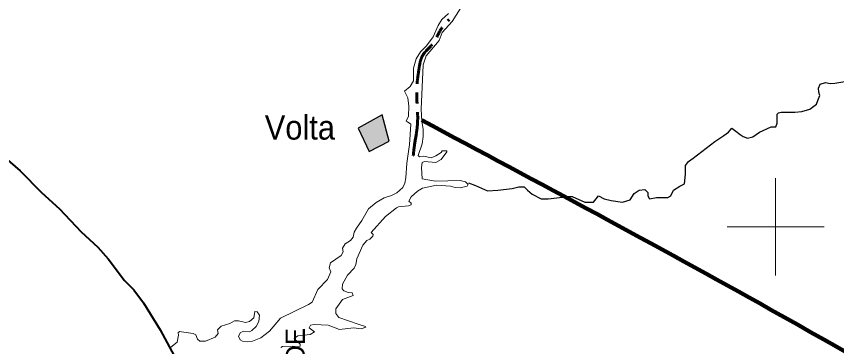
# Model space of a CAD drawing. Extents: x 553962 to 842807, y 8883888 to 9032388.
# Drawn here: x 584337 to 601258, y 8972533 to 8979336 of the extents above; entities that cross this region are included whole.
import ezdxf

# ---------------------------------------------------------------- set-up
doc = ezdxf.new("R2010")
doc.units = 0
doc.header["$LTSCALE"] = 150
doc.linetypes.add('LONG_DASH_SHORT_DASH', pattern=[9.9, 6, -1.2, 1.5, -1.2])
for name, color, linetype, lineweight in [('12', 7, 'Continuous', 25), ('2', 7, 'Continuous', 13), ('21', 7, 'Continuous', 25), ('24', 7, 'Continuous', 25), ('25', 7, 'Continuous', 13), ('7', 7, 'LONG_DASH_SHORT_DASH', 60), ('9', 7, 'Continuous', 90)]:
    doc.layers.add(name, color=color, linetype=linetype, lineweight=lineweight)
doc.layers.add('41', color=7, linetype='Continuous')
doc.layers.add('50', color=7, linetype='Continuous')

msp = doc.modelspace()

# ---------------------------------------------------------------- hatches: boundary and pattern name
at = {"layer": '21'}
msp.add_hatch(color=256, dxfattribs=at).paths.add_polyline_path([(591387.2, 8977029.8), (591614.3, 8976550.1), (592028.7, 8976768.6), (591880.1, 8977309.9)])

# ---------------------------------------------------------------- linework, layer by layer
at = {"layer": '12', "lineweight": 40}
msp.add_lwpolyline([(584108.1, 8976423.9), (584414.4, 8976152.1), (584852.4, 8975709.9), (585227.8, 8975368.9), (585671, 8974897.7), (586014.6, 8974582.2), (586230.8, 8974340.1), (586568.3, 8973894.4), (586761.1, 8973701.7), (586961.6, 8973436.3), (587301, 8972874.3), (587640.4, 8972251.7)], dxfattribs=at)
at = {"layer": '2'}
for p, q in [((600000, 8974000), (600000, 8976000)), ((599000, 8975000), (601000, 8975000))]:
    msp.add_line(p, q, dxfattribs=at)
at = {"layer": '21'}
msp.add_lwpolyline([(591387.2, 8977029.8), (591614.3, 8976550.1), (592028.7, 8976768.6), (591880.1, 8977309.9)], close=True, dxfattribs=at)
at = {"layer": '24'}
msp.add_lwpolyline([(593663, 8975903.4), (593811, 8975854), (594057.8, 8975738.8), (594271.7, 8975755.3), (594567.8, 8975788.2), (594699.4, 8975821.1), (594814.5, 8975821.1), (594880.3, 8975755.3), (594979, 8975673), (595160, 8975574.2), (595308.1, 8975574.2), (595719.3, 8975623.6), (595801.6, 8975623.6), (596064.8, 8975508.3), (596163.5, 8975508.3), (596245.7, 8975508.3), (596295.1, 8975574.2), (596344.4, 8975640), (596459.6, 8975574.2), (596607.7, 8975541.3), (596838, 8975508.3), (597002.5, 8975557.7), (597084.7, 8975689.4), (597183.4, 8975755.3), (597298.6, 8975771.7), (597364.4, 8975705.9), (597364.4, 8975640), (597397.3, 8975574.2), (597545.3, 8975607.1), (597627.6, 8975607.1), (597775.7, 8975607.1), (597841.5, 8975640), (597890.8, 8975755.3), (598022.4, 8975837.6), (598121.1, 8975887), (598137.6, 8976084.5), (598137.6, 8976265.6), (598203.4, 8976347.9), (598302.1, 8976413.7), (598746.2, 8976759.4), (598932.5, 8976878.8), (599027.9, 8976952.2), (599093.9, 8977032.9), (599181.9, 8976974.2), (599269.9, 8976900.8), (599328.6, 8976864.1), (599416.6, 8976827.4), (599526.6, 8976856.8), (599665.9, 8976952.2), (599907.9, 8977062.2), (600003.2, 8977062.2), (600032.6, 8977135.6), (600032.6, 8977238.3), (600032.6, 8977319.1), (600061.9, 8977348.4), (600113.2, 8977363.1), (600274.6, 8977363.1), (600399.2, 8977363.1), (600538.6, 8977377.8), (600707.2, 8977421.8), (600846.6, 8977524.5), (600868.6, 8977605.3), (600912.6, 8977708), (600890.6, 8977774), (600883.2, 8977854.8), (600919.9, 8977942.8), (601029.9, 8977972.2), (601125.3, 8977950.2), (601220.6, 8977957.5), (601469.9, 8978001.5)], dxfattribs=at)
at = {"layer": '25'}
for points in [[(593541.1, 8979568.9), (593326.1, 8979230.3), (593118.1, 8979003.2), (593056.2, 8978837.1), (592788.7, 8978522.9), (592727, 8978339.3), (592684.6, 8977422.8), (592701.6, 8977167.9), (592731.3, 8977014.7), (592731.4, 8976862.7), (592710.1, 8976709.1), (592625.3, 8976466.7), (592653, 8976439.2), (592742.2, 8976458.1), (592894.9, 8976424.2), (592992.8, 8976460.4), (593098.8, 8976528.3), (593123.6, 8976567.4), (593214.3, 8976567.6), (593214.6, 8976559.7)], [(593541.1, 8979568.9), (593326.1, 8979230.3), (593118.1, 8979003.2), (593056.2, 8978837.1), (592788.7, 8978522.9), (592727, 8978339.3), (592684.6, 8977422.8), (592701.6, 8977167.9), (592731.3, 8977014.7), (592731.4, 8976862.7), (592710.1, 8976709.1), (592625.3, 8976466.7), (592653, 8976439.2), (592742.2, 8976458.1), (592894.9, 8976424.2), (592992.8, 8976460.4), (593098.8, 8976528.3), (593123.6, 8976567.4), (593214.3, 8976567.6), (593214.6, 8976559.7)], [(592340.2, 8977796.1), (592463.6, 8977889.9), (592529.4, 8978006.6), (592531.7, 8978272), (592582.8, 8978459.4), (592672, 8978608.1), (592799.5, 8978729.2), (592937.2, 8978913.6), (593037.2, 8979147.4), (593113.6, 8979274.7), (593249.5, 8979396.5)], [(592340.2, 8977796.1), (592463.6, 8977889.9), (592529.4, 8978006.6), (592531.7, 8978272), (592582.8, 8978459.4), (592672, 8978608.1), (592799.5, 8978729.2), (592937.2, 8978913.6), (593037.2, 8979147.4), (593113.6, 8979274.7), (593249.5, 8979396.5)], [(592403.5, 8977160.8), (592376.8, 8977178.1), (592423.3, 8977282.6), (592436.1, 8977486), (592410.8, 8977655.4), (592340.2, 8977796.1)], [(592403.5, 8977160.8), (592376.8, 8977178.1), (592423.3, 8977282.6), (592436.1, 8977486), (592410.8, 8977655.4), (592340.2, 8977796.1)], [(589256.8, 8973257.4), (589304.8, 8973250.5), (589349.5, 8973181.3), (589336.7, 8973046.6), (589282, 8972943.2), (589197.1, 8972864.3), (589143.7, 8972836.4), (589028.8, 8972846.9), (588963.2, 8972823.6), (588920.5, 8972745), (588956.7, 8972674.9), (589003.3, 8972647.2), (589105, 8972632.4), (589208.9, 8972641.3), (589377.1, 8972711), (589557.5, 8972848.9), (589783.1, 8973121.1), (590364.9, 8973397.1), (590439.2, 8973448.1), (590558.2, 8973707.2), (590751.6, 8973917.8), (590821.5, 8974070.5), (590792, 8974157.8), (590815.2, 8974257.2), (591040.4, 8974410.4), (591076.5, 8974482.4), (591063.8, 8974558.8), (591121.2, 8974648.3), (591227.2, 8974720.4), (591282.6, 8974788.8), (591308.2, 8974890.7), (591350.1, 8974974.6), (591465.3, 8975128.4), (591603.2, 8975370.3), (591756.1, 8975500), (591922, 8975597.8), (592075.7, 8975644.8), (592185.6, 8975697.8), (592308.6, 8975810.4), (592349.1, 8975899.9), (592374.4, 8976007.6), (592391.5, 8976313.7), (592449, 8976697.9), (592471.9, 8977116.8), (592403.5, 8977160.8)], [(589256.8, 8973257.4), (589304.8, 8973250.5), (589349.5, 8973181.3), (589336.7, 8973046.6), (589282, 8972943.2), (589197.1, 8972864.3), (589143.7, 8972836.4), (589028.8, 8972846.9), (588963.2, 8972823.6), (588920.5, 8972745), (588956.7, 8972674.9), (589003.3, 8972647.2), (589105, 8972632.4), (589208.9, 8972641.3), (589377.1, 8972711), (589557.5, 8972848.9), (589783.1, 8973121.1), (590364.9, 8973397.1), (590439.2, 8973448.1), (590558.2, 8973707.2), (590751.6, 8973917.8), (590821.5, 8974070.5), (590792, 8974157.8), (590815.2, 8974257.2), (591040.4, 8974410.4), (591076.5, 8974482.4), (591063.8, 8974558.8), (591121.2, 8974648.3), (591227.2, 8974720.4), (591282.6, 8974788.8), (591308.2, 8974890.7), (591350.1, 8974974.6), (591465.3, 8975128.4), (591603.2, 8975370.3), (591756.1, 8975500), (591922, 8975597.8), (592075.7, 8975644.8), (592185.6, 8975697.8), (592308.6, 8975810.4), (592349.1, 8975899.9), (592374.4, 8976007.6), (592391.5, 8976313.7), (592449, 8976697.9), (592471.9, 8977116.8), (592403.5, 8977160.8)], [(593214.6, 8976559.7), (593215.2, 8976544.7), (593099, 8976390.4), (592986.9, 8976322.5), (592758.7, 8976343.4), (592708.2, 8976324.4), (592695.2, 8976224.5), (592709.9, 8975991.5), (592983.9, 8975944.1), (593493.9, 8975956.8), (593602.1, 8975927.4), (593649.1, 8975881.7)], [(593214.6, 8976559.7), (593215.2, 8976544.7), (593099, 8976390.4), (592986.9, 8976322.5), (592758.7, 8976343.4), (592708.2, 8976324.4), (592695.2, 8976224.5), (592709.9, 8975991.5), (592983.9, 8975944.1), (593493.9, 8975956.8), (593602.1, 8975927.4), (593649.1, 8975881.7)], [(593649.1, 8975881.7), (593655, 8975876), (593638.1, 8975835.7), (593493.9, 8975806), (593392, 8975812.4), (593294, 8975840), (593001.4, 8975857), (592713.8, 8975797.2), (592610.3, 8975731.6), (592482.8, 8975616.5), (592429.9, 8975529.9), (592480.5, 8975487.5), (592478.3, 8975455.5), (592423.1, 8975432.1), (592219.4, 8975410.8), (592178.8, 8975393.7), (591951.5, 8975211), (591658.9, 8974884.4), (591696.9, 8974843.5), (591690.4, 8974805.5), (591629, 8974746.2), (591569.4, 8974716.2), (591482.2, 8974622.5), (591361.3, 8974342.6), (591339.9, 8974225.6), (591302.4, 8974150.2), (591167.7, 8974002.3), (591061.7, 8973815.6), (591059.6, 8973722.4), (591091.3, 8973677.8), (591182.8, 8973643.6), (591261.3, 8973639.2), (591286.8, 8973584.3), (591065.8, 8973500.9), (590925.8, 8973310), (590930.2, 8973216.3), (590989.7, 8973133.6), (591386.4, 8972993.6), (591539.1, 8972948.4), (591544.1, 8972929.1)], [(593649.1, 8975881.7), (593655, 8975876), (593638.1, 8975835.7), (593493.9, 8975806), (593392, 8975812.4), (593294, 8975840), (593001.4, 8975857), (592713.8, 8975797.2), (592610.3, 8975731.6), (592482.8, 8975616.5), (592429.9, 8975529.9), (592480.5, 8975487.5), (592478.3, 8975455.5), (592423.1, 8975432.1), (592219.4, 8975410.8), (592178.8, 8975393.7), (591951.5, 8975211), (591658.9, 8974884.4), (591696.9, 8974843.5), (591690.4, 8974805.5), (591629, 8974746.2), (591569.4, 8974716.2), (591482.2, 8974622.5), (591361.3, 8974342.6), (591339.9, 8974225.6), (591302.4, 8974150.2), (591167.7, 8974002.3), (591061.7, 8973815.6), (591059.6, 8973722.4), (591091.3, 8973677.8), (591182.8, 8973643.6), (591261.3, 8973639.2), (591286.8, 8973584.3), (591065.8, 8973500.9), (590925.8, 8973310), (590930.2, 8973216.3), (590989.7, 8973133.6), (591386.4, 8972993.6), (591539.1, 8972948.4), (591544.1, 8972929.1)], [(587744.4, 8972835.9), (587983.9, 8972804.3), (588036.8, 8972776.6), (588075, 8972687.6), (588119.6, 8972647.3), (588237.5, 8972640.8), (588435.9, 8972723.7), (588499.7, 8972804.5), (588483.1, 8972879), (588561.7, 8972951.1), (588739.8, 8973006.3), (588835.7, 8973065.7), (588918.6, 8973063.5), (589063, 8973031.8), (589147.9, 8973046.8), (589234.5, 8973124.8), (589252.7, 8973258), (589256.8, 8973257.4)], [(587744.4, 8972835.9), (587983.9, 8972804.3), (588036.8, 8972776.6), (588075, 8972687.6), (588119.6, 8972647.3), (588237.5, 8972640.8), (588435.9, 8972723.7), (588499.7, 8972804.5), (588483.1, 8972879), (588561.7, 8972951.1), (588739.8, 8973006.3), (588835.7, 8973065.7), (588918.6, 8973063.5), (589063, 8973031.8), (589147.9, 8973046.8), (589234.5, 8973124.8), (589252.7, 8973258), (589256.8, 8973257.4)], [(591544.1, 8972929.1), (591451.2, 8972895.9), (591293, 8972921.2), (591000.3, 8972885.2), (590771.4, 8972974.2), (590482, 8972987.1), (590400.9, 8972976.4), (590375.5, 8972917.5), (590487.9, 8972834.1), (590400.8, 8972781.1), (590146.4, 8972755.6), (590069.9, 8972700.4), (590188.4, 8972581.5), (590190.6, 8972539), (590153.7, 8972526.2), (590022.9, 8972543.1), (589823.3, 8972534.6), (589789.5, 8972511.4)], [(591544.1, 8972929.1), (591451.2, 8972895.9), (591293, 8972921.2), (591000.3, 8972885.2), (590771.4, 8972974.2), (590482, 8972987.1), (590400.9, 8972976.4), (590375.5, 8972917.5), (590487.9, 8972834.1), (590400.8, 8972781.1), (590146.4, 8972755.6), (590069.9, 8972700.4), (590188.4, 8972581.5), (590190.6, 8972539), (590153.7, 8972526.2), (590022.9, 8972543.1), (589823.3, 8972534.6), (589789.5, 8972511.4)], [(587520.6, 8972519.8), (587652.2, 8972626), (587681.8, 8972766), (587674.8, 8972821.7), (587705.8, 8972841), (587744.4, 8972835.9)], [(587520.6, 8972519.8), (587652.2, 8972626), (587681.8, 8972766), (587674.8, 8972821.7), (587705.8, 8972841), (587744.4, 8972835.9)]]:
    msp.add_lwpolyline(points, dxfattribs=at)
at = {"layer": '7'}
msp.add_spline([(592525.2, 8976466.9), (592528.1, 8976506.5), (592612.5, 8977139.6), (592595.6, 8977840.2), (592646.2, 8978279.2), (592713.7, 8978524), (592916.2, 8978760.3), (593118.7, 8979106.4), (593264.9, 8979274.8)], degree=3, dxfattribs=at)
at = {"layer": '9'}
msp.add_spline([(592698.5, 8977198.4), (599903.5, 8973292.7), (608459.2, 8968138.2), (612674.8, 8965332.6), (616842, 8962096.4), (620005, 8958671.2), (621134, 8957974.7), (621473.4, 8956805.3), (621586.2, 8956597.5)], degree=3, dxfattribs=at)

# ---------------------------------------------------------------- texts
at = {"layer": '41', "width": 0.95}
msp.add_text('Volta', height=500, dxfattribs=at).set_placement((589461.3, 8976797.6))
at = {"layer": '50'}
msp.add_text('RESERVATÓRIO DE', height=400, rotation=90, dxfattribs=at).set_placement((590289.9, 8967775.2))

doc.saveas('drawing.dxf')
